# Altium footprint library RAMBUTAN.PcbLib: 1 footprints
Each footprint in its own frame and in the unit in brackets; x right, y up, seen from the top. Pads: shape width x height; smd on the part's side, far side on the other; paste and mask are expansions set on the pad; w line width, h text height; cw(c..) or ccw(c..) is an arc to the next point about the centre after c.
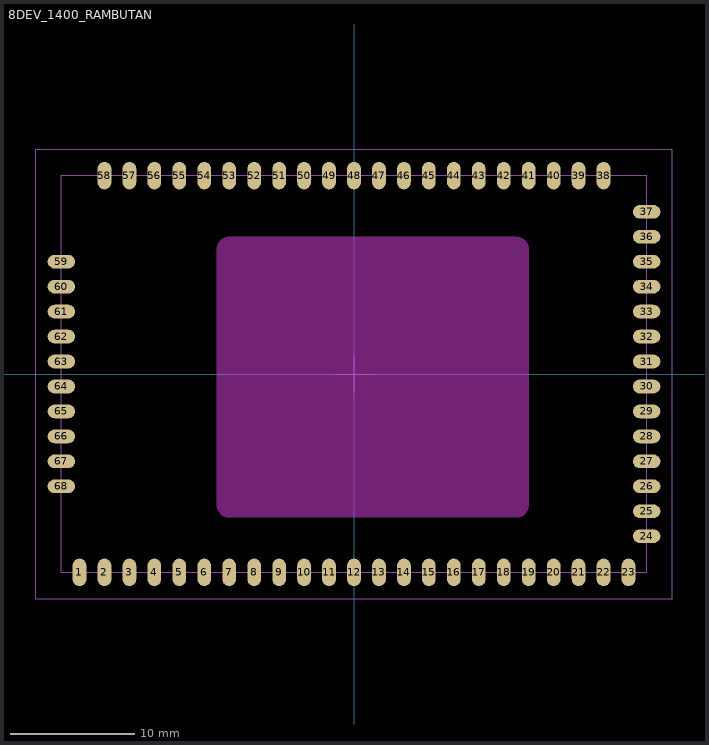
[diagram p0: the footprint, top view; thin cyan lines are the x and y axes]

## 8DEV_1400_RAMBUTAN [mm] "Dual-band module."
height 4.42
pads (68):
  rrect100% 1.1x2.2 smd paste+0.05: 1(-22,-15.9) 2(-20,-15.9) 3(-18,-15.9) 4(-16,-15.9) 5(-14,-15.9) 6(-12,-15.9) 7(-10,-15.9) 8(-8,-15.9) 9(-6,-15.9) 10(-4,-15.9) 11(-2,-15.9) 12(0,-15.9) 13(2,-15.9) 14(4,-15.9) 15(6,-15.9) 16(8,-15.9) 17(10,-15.9) 18(12,-15.9) 19(14,-15.9) 20(16,-15.9) 21(18,-15.9) 22(20,-15.9) 23(22,-15.9) 38(20,15.9) 39(18,15.9) 40(16,15.9) 41(14,15.9) 42(12,15.9) 43(10,15.9) 44(8,15.9) 45(6,15.9) 46(4,15.9) 47(2,15.9) 48(0,15.9) 49(-2,15.9) 50(-4,15.9) 51(-6,15.9) 52(-8,15.9) 53(-10,15.9) 54(-12,15.9) 55(-14,15.9) 56(-16,15.9) 57(-18,15.9) 58(-20,15.9)
  rrect100% 2.2x1.1 smd paste+0.05: 24(23.45,-13) 25(23.45,-11) 26(23.45,-9) 27(23.45,-7) 28(23.45,-5) 29(23.45,-3) 30(23.45,-1) 31(23.45,1) 32(23.45,3) 33(23.45,5) 34(23.45,7) 35(23.45,9) 36(23.45,11) 37(23.45,13) 59(-23.45,9) 60(-23.45,7) 61(-23.45,5) 62(-23.45,3) 63(-23.45,1) 64(-23.45,-1) 65(-23.45,-3) 66(-23.45,-5) 67(-23.45,-7) 68(-23.45,-9)
Top Paste:
  drawing of 72 lines, arcs and shapes, not listed
Keep-Out Layer:
  board cut-out: -11,-10.5 -11,10 -11,10.098 -10.962,10.292 -10.886,10.474 -10.777,10.637 -10.637,10.777 -10.474,10.886 -10.292,10.962 -10.098,11 -10,11 13,11 13.098,11 13.292,10.962 13.474,10.886 13.637,10.777 13.777,10.637 13.886,10.474 13.962,10.292 14,10.098 14,10 14,-10.5 14,-10.598 13.962,-10.792 13.886,-10.974 13.777,-11.137 13.637,-11.277 13.474,-11.386 13.292,-11.462 13.098,-11.5 13,-11.5 -10,-11.5 -10.098,-11.5 -10.292,-11.462 -10.474,-11.386 -10.637,-11.277 -10.777,-11.137 -10.886,-10.974 -10.962,-10.792 -11,-10.598
Mechanical 14:
  drawing of 3590 lines, arcs and shapes, not listed
  text ".comment" at -18.797,8.766 h1.12
  text ".designator" at -18.847,10.391 h1.5
Mechanical 15:
  lines w0.1: 0,-1.5 0,1.5 0,0 ; 0,0 -1.5,0 1.5,0 0,0 ; -25.5,-18 -25.5,18 25.5,18 25.5,-18 -25.5,-18
3D body: height 3.52, standoff 0, extent -23.449,-15.903 23.455,15.933
3D body: height 0.9, standoff -0.9, extent -9.975,-10.55 13,10.125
